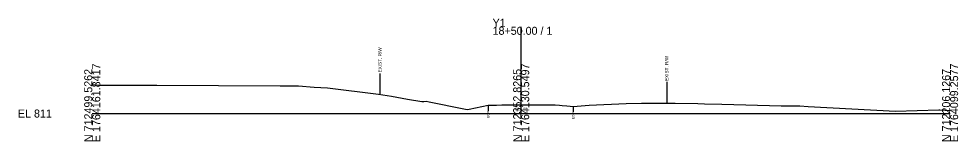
# Model space of a CAD drawing. Extents: x -26 to 1303, y -10 to 9524.
# Drawn here: x -25.7 to 302.8, y 8490.3 to 8533.1 of the extents above; entities that cross this region are included whole.
import ezdxf

# ---------------------------------------------------------------- set-up
doc = ezdxf.new("R2010")
doc.units = 0
for name, color, linetype in [('Default', 7, 'Continuous'), ('Exist Cross Section Cell', 7, 'Continuous'), ('Exist XS Center Line Elevation Label', 7, 'Continuous'), ('Exist XS Ground Line', 7, 'Continuous'), ('Old_Level_10', 7, 'Continuous')]:
    doc.layers.add(name, color=color, linetype=linetype)

msp = doc.modelspace()

# ---------------------------------------------------------------- linework, layer by layer
at = {"layer": 'Exist Cross Section Cell'}
for p, q in [((150, 8500), (150, 8530.35)), ((0, 8500), (150, 8500)), ((150, 8500), (300, 8500))]:
    msp.add_line(p, q, dxfattribs=at)
at = {"layer": 'Exist XS Ground Line'}
msp.add_lwpolyline([(0, 8510.1), (2.65, 8509.97), (3, 8509.97), (3.81, 8509.97), (4.91, 8509.97), (5.72, 8509.97), (10.93, 8509.97), (22.55, 8509.97), (65.74, 8509.73), (69.4, 8509.72), (72.18, 8509.69), (77.64, 8509.22), (82.22, 8508.93), (100.05, 8506.73), (101.62, 8506.52), (104.63, 8506.11), (110.27, 8505.08), (115.21, 8504.25), (115.96, 8504.16), (116.74, 8504.33), (117.8, 8504.11), (130, 8501.66), (131.14, 8501.42), (131.8, 8501.56), (138.43, 8502.91), (139.01, 8502.91), (140.19, 8502.95), (140.5, 8502.96), (141.39, 8502.96), (143.21, 8502.99), (143.94, 8502.99), (146.64, 8503.02), (149.06, 8503.07), (150, 8503.08), (150.45, 8503.09), (151.12, 8503.08), (152.29, 8503.06), (152.85, 8503.07), (154.17, 8503.06), (156.21, 8503.04), (156.72, 8503.04), (158.63, 8503.03), (159.31, 8503.03), (161.15, 8503.01), (161.84, 8502.99), (163.38, 8502.89), (164.39, 8502.81), (165.96, 8502.65), (167.13, 8502.53), (168.16, 8502.5), (173.78, 8502.91), (186.76, 8503.51), (192.05, 8503.62), (202.4, 8503.67), (203.88, 8503.67), (211.73, 8503.47), (214.11, 8503.41), (220.16, 8503.24), (224.33, 8503.14), (228.59, 8503.06), (240.98, 8502.69), (243.13, 8502.65), (247.5, 8502.65), (250.35, 8502.43), (280.89, 8500.85), (296.01, 8501.29), (296.46, 8501.28), (300, 8501.05)], dxfattribs=at)
at = {"layer": 'Old_Level_10'}
for p, q in [((100.6, 8514.06), (100.6, 8506.66)), ((200.89, 8511.07), (200.89, 8503.67)), ((138.43, 8502.91), (138.43, 8500.86)), ((168.16, 8502.5), (168.16, 8500.45))]:
    msp.add_line(p, q, dxfattribs=at)

# ---------------------------------------------------------------- texts
at = {"layer": 'Default'}
msp.add_text('-', height=0.0001, dxfattribs=at).set_placement((0, 8500))
at = {"layer": 'Exist Cross Section Cell'}
for s, p in [('Y1', (140, 8530.35)), ('18+50.00 / 1', (140, 8527.55)), ('EL 811', (-26, 8498.6))]:
    msp.add_text(s, height=2.8, dxfattribs=at).set_placement(p)
for s, p in [('E 1764161.8417', (2.8, 8490)), ('E 1764130.5497', (152.8, 8490)), ('E 1764099.2577', (302.8, 8490)), ('N 712499.5262', (0, 8490)), ('N 712352.8265', (150, 8490)), ('N 712206.1267', (300, 8490))]:
    msp.add_text(s, height=2.8, rotation=90, dxfattribs=at).set_placement(p)
at = {"layer": 'Exist XS Center Line Elevation Label'}
msp.add_text('814.08', height=1, dxfattribs=at).set_placement((147.98, 8501.08))
at = {"layer": 'Old_Level_10'}
for s, height, p in [('EXIST. R/W', 1.181, (101.19, 8514.36)), ('EXIST. R/W', 1.181, (201.49, 8511.37)), ('EOP', 0.787, (138.82, 8498.46)), ('EOP', 0.787, (168.55, 8498.05))]:
    msp.add_text(s, height=height, rotation=90, dxfattribs=at).set_placement(p)

doc.saveas('drawing.dxf')
